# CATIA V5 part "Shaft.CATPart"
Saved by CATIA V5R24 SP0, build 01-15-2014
Part number: Shaft
Bounding box of the stored display mesh (mm): x -30 to 30, y -55 to 26, z -30 to 30
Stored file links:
  \\cdl-main\FTPSERVER\Minsik\2016\2\Shaft.CATPart
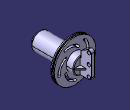
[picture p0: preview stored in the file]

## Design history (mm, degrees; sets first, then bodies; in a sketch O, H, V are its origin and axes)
Set1
  Sketch1 on zx-plane, origin (0, 0, 0), H (-1, 0, 0), V (0, 0, 1)
    circle A1 centre (0, 0) radius 30
    radius A1 = 30
Body1 (main body)
  Pad1: profile Sketch1, direction (0, -1, 0), length 5
  Sketch2 on zx-plane, origin (0, 0, 0), H (-1, 0, 0), V (0, 0, 1)
    circle A1 centre (0, 0) radius 12.5
    radius A1 = 12.5
  Pad2: profile Sketch2, direction (0, 1, 0), length 10, opposite side length 55
  Chamfer1: length 1, angle 45, on edge [face of Pad2 from Sketch2.A1 | end face of Pad2]
  Chamfer2: length 5, angle 45, on edge [start face of Pad2 | face of Pad2 from Sketch2.A1]
  Sketch3 on yz-plane, origin (0, 0, 0), H (0, 1, 0), V (0, 0, 1)
    line L1 (-3.5, 33.9308) -> (-3.5, 28.5)
    line L2 (-3.5, 28.5) -> (-1.5, 28.5)
    line L3 (-1.5, 28.5) -> (-1.5, 33.9708)
    reference projected line E1 (0, 30) -> (0, -30) from edge [face of Pad1 from Sketch1.A1 | start face of Pad1]
    axis line L4 (23.9648, 0) -> (-10.9485, 0)
    point P5 (23.9648, 0)
    distance L3 E1 = 1.5
    distance L3 L1 = 2
    distance L2 H = 28.5
    vertical: L1 V, L3 V
    horizontal: L2 H, L4 H
    coincidence: P5 H
  Groove1: profile Sketch3, axis Sketch3.L4, angle 360
  Sketch4 on yz-plane, origin (0, 0, 0), H (0, 1, 0), V (0, 0, 1)
    line L1 (7.6852, 11) -> (11, 11)
    line L2 (11, 11) -> (11, 17.0152)
    line L3 (13.5, 21.3453) -> (20.75, 25.5311)
    line L4 (26, 22.5) -> (26, -7.5)
    line L5 (22.5, -11) -> (7.6852, -11)
    line L6 (7.6852, -11) -> (7.6852, 11)
    reference projected line E1 (10, 11.5) -> (10, -11.5) from edge [face of Chamfer1 | end face of Pad2]
    arc A1 centre (22.5, -7.5) radius 3.5 from (26, -7.5) to (22.5, -11) cw
    point P6 (22.5, -7.5)
    arc A2 centre (22.5, 22.5) radius 3.5 from (20.75, 25.5311) to (26, 22.5) cw
    point P9 (22.5, 22.5)
    circle A3 centre (22.5, -7.5) radius 2.5
    circle A4 centre (22.5, 22.5) radius 2.5
    circle A5 centre (22.5, 7.5) radius 2.5
    point P10 (22.5, 7.5)
    arc A6 centre (16, 17.0152) radius 5 from (11, 17.0152) to (13.5, 21.3453) cw
    angle L3 L4 = 60
    distance L2 L4 = 15
    distance L1 H = 11
    distance L2 E1 = 1
    distance L5 H = 11
    radius A1 = 3.5
    radius A2 = 3.5
    radius A3 = 2.5
    radius A4 = 2.5
    distance P9 P6 = 30
    radius A5 = 2.5
    distance P10 P6 = 15
    distance P10 P6 H = 0
    radius A6 = 5
    horizontal: L1 H, L5 H
    vertical: L2 V, L4 V, L6 V
    tangency: A1 L4, A1 L5, A2 L3, A2 L4, A6 L2, A6 L3
  Pad3: profile Sketch4, direction (1, 0, 0), length 2.5, mirrored extent
  Sketch5 on xy-plane, origin (0, 0, 0), H (1, 0, 0), V (0, 1, 0)
    line L1 (2.5, 18) -> (10.5, 10)
    point P1 (2.5, 18)
    point P2 (10.5, 10)
    reference projected line E1 (-11.5, 10) -> (11.5, 10) from edge [face of Chamfer1 | end face of Pad2]
    reference projected line E2 (-11.5, 10) -> (11.5, 10) from edge [face of Chamfer1 | end face of Pad2]
    reference projected line E3 (2.5, 20.75) -> (2.5, 13.5) from edge [face of Pad3 from Sketch4.L3 | end face of Pad3]
    distance P1 E1 = 8
    angle L1 H = 45
    coincidence: P2 E2, P1 E3
  Stiffener1: ExtendedProfile Sketch5, ThicknessTop 0, ThicknessValue 2
  Mirror1: of Stiffener1, about yz-plane
  Sketch6 on start face of Pad1, origin (0, 0, 0), H (-1, 0, 0), V (0, 0, 1)
    construction arc A1 centre (1.0012, 8.1264) radius 17.5 from (16.5, 0) to (14, 19.8431) ccw
    point P1 (1.0012, 8.1264)
    point P2 (16.5, 0)
    point P3 (14, 19.8431)
    arc A2 centre (16.5, 0) radius 1.5 from (17.8285, -0.6965) to (15.1715, 0.6966) cw
    arc A3 centre (14, 19.8431) radius 1.5 from (12.8858, 18.8388) to (15.1142, 20.8474) cw
    arc A4 centre (1.0012, 8.1264) radius 16 from (15.1715, 0.6966) to (12.8858, 18.8388) ccw
    arc A5 centre (1.0012, 8.1264) radius 19 from (15.1142, 20.8474) to (17.8285, -0.6965) cw
    radius A3 = 1.5
    distance P2 P3 = 20
    radius A5 = 19
    distance P3 V = 14
    distance P2 V = 16.5
    tangency: A4 A3, A3 A5, A5 A2, A2 A4
    concentricity: A4 P1, A5 P1
    coincidence: P2 H
  Pocket1: profile Sketch6, direction (0, -1, 0), through (limit type 6)
  CircPattern1: of Pocket1, instances 6, angular step 72, axis from start face of Pad1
